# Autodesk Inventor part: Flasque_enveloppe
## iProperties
Shininess: 64.0
Length Units: 11269
Angle Units: 11279
Time Units: 11290
Mass Units: 11283
Length Display Precision: 3
Angle Display Precision: 2
Compacted: True
Part Number: Flasque_enveloppe
Document SubType Name: Modeling
Created: 2008-02
Material: Par défaut
Designer: Pascal
Density: 1 g/cm^3
Density: 0.0
Volumn: 0.0
Area: 0.0
PropertySet Name: Model Information
Control State: 0
Master: False
Checked Out: False
DESIGNATION: Flasque enveloppe
Author: Pascal
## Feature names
1. Extrusion1
